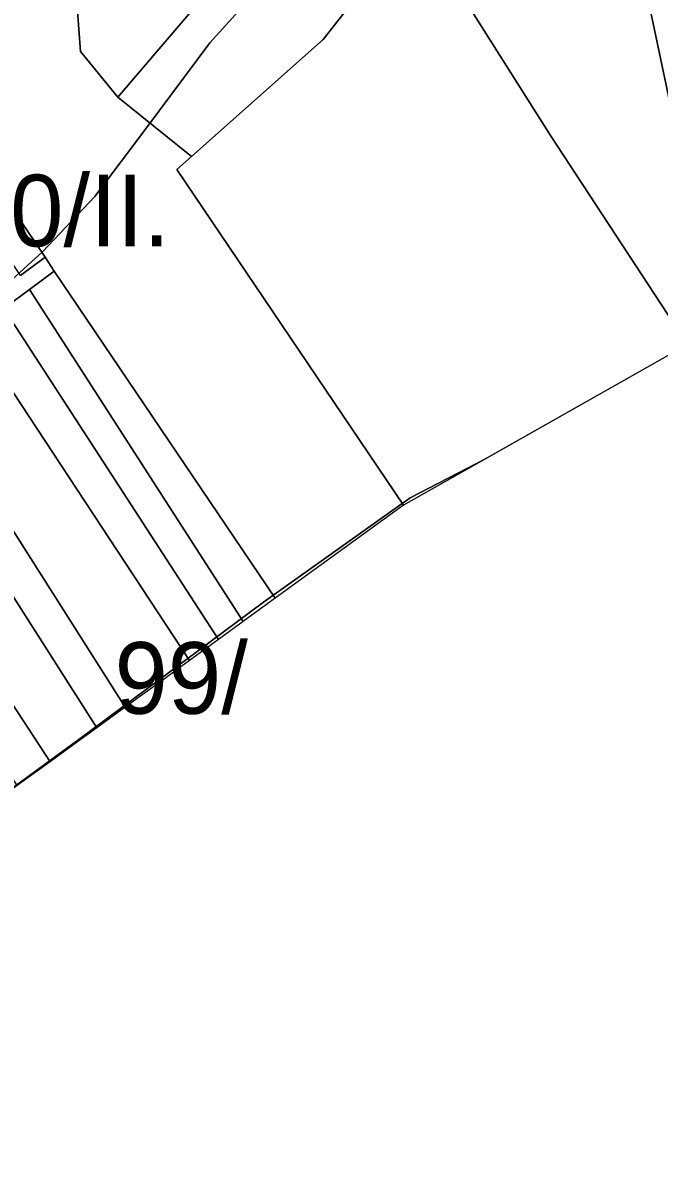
# Model space of a CAD drawing. Extents: x -535894 to -532827, y -1165802 to -1163635.
# Drawn here: x -534025 to -533891.9, y -1165422.7 to -1165184 of the extents above; entities that cross this region are included whole.
import ezdxf

# ---------------------------------------------------------------- set-up
doc = ezdxf.new("R2010")
doc.units = 0
for name, color, linetype in [('BPEJ_s', 7, 'Continuous'), ('orna_s', 7, 'Continuous'), ('ostatni_s', 7, 'Continuous'), ('trav_porost_s', 7, 'Continuous')]:
    doc.layers.add(name, color=color, linetype=linetype)

msp = doc.modelspace()

# ---------------------------------------------------------------- linework, layer by layer
at = {"layer": 'BPEJ_s'}
for points in [[(-533970.41, -1165171.07), (-533985.872, -1165188.218), (-533999.16, -1165206.031), (-534009.91, -1165220.44), (-534020.91, -1165231.99), (-534035.084, -1165244.865), (-534056.9, -1165261.54), (-534075.955, -1165274.993), (-534079.332, -1165277.377), (-534105.4, -1165298.17), (-534125.07, -1165313.86), (-534136.06, -1165324.773), (-534150.4, -1165346.2), (-534161.87, -1165369.29), (-534178.11, -1165393.66), (-534186.226, -1165403.375), (-534198.82, -1165412.93), (-534213.249, -1165419.389), (-534226.966, -1165422.497), (-534241.03, -1165422.65), (-534254.891, -1165420.26), (-534261.74, -1165417.867), (-534281.75, -1165380.99)], [(-534136.06, -1165324.773), (-534125.07, -1165313.86), (-534105.4, -1165298.17), (-534079.332, -1165277.377), (-534075.955, -1165274.993), (-534056.9, -1165261.54), (-534035.084, -1165244.865), (-534020.91, -1165231.99), (-534009.91, -1165220.44), (-533999.16, -1165206.031), (-533985.872, -1165188.218), (-533970.41, -1165171.07)], [(-533885.93, -1165251.42), (-533928.089, -1165275.274), (-533943.99, -1165283.5), (-533974.66, -1165305.36), (-534013.02, -1165333.89), (-534079.092, -1165382.22)]]:
    msp.add_lwpolyline(points, dxfattribs=at)
msp.add_lwpolyline([(-534075.22, -1165379.41), (-534079.092, -1165382.22), (-534013.02, -1165333.89), (-533974.66, -1165305.36), (-533943.99, -1165283.5), (-533928.089, -1165275.274), (-533945.33, -1165285.03), (-533972.2, -1165304.55), (-533978.9, -1165309.42), (-533984.1, -1165313.19), (-533990.15, -1165317.59), (-533996.63, -1165322.3), (-534003.61, -1165327.37), (-534009.54, -1165331.68), (-534014.32, -1165335.17), (-534019.31, -1165338.8), (-534026.18, -1165343.78), (-534031.82, -1165347.88), (-534037.71, -1165352.16), (-534044.14, -1165356.83), (-534052.73, -1165363.08), (-534059.04, -1165367.66), (-534067.65, -1165373.91)], close=True, dxfattribs=at)
at = {"layer": 'orna_s'}
msp.add_lwpolyline([(-534053.42, -1165184.18), (-534020.37, -1165233.16), (-534025.49, -1165236.98), (-534057.5, -1165188.56)], close=True, dxfattribs=at)
at = {"layer": 'ostatni_s'}
msp.add_lwpolyline([(-534025.49, -1165236.98), (-534020.37, -1165233.16), (-534018.44, -1165236.03), (-534023.58, -1165239.87), (-534028.98, -1165243.88)], dxfattribs=at)
at = {"layer": 'trav_porost_s'}
for points in [[(-533885.93, -1165251.42), (-533914.6, -1165207.64), (-533942.82, -1165162.9), (-533928.42, -1165147.92), (-533922.67, -1165144.99), (-533917.7, -1165142.45), (-533927.15, -1165125.06), (-533934.45, -1165116.87), (-533962.53, -1165085.32), (-533960.64, -1165083.51), (-533944.91, -1165074.95), (-533943.82, -1165067.47), (-533942.64, -1165066.34), (-533932.89, -1165078.2), (-533921.87, -1165077.16), (-533901.06, -1165073.37), (-533870.09, -1165067.22)], [(-533864.82, -1165157.28), (-533899.27, -1165133.08), (-533903.4, -1165135.17), (-533879.59, -1165248.35)]]:
    msp.add_lwpolyline(points, dxfattribs=at)
for points in [[(-533962.53, -1165085.32), (-533934.45, -1165116.87), (-533940.8, -1165124.3), (-534005.15, -1165199.61), (-534012.92, -1165190.05), (-534014.17, -1165173.12), (-534019.14, -1165162.52), (-534024.54, -1165159.35), (-534021.42, -1165157.14), (-534022.96, -1165151.54), (-534010.91, -1165138.64), (-533976.02, -1165098.2)], [(-533940.8, -1165124.3), (-533927.13, -1165137.47), (-533922.67, -1165144.99), (-533928.42, -1165147.92), (-533942.82, -1165162.9), (-533962.19, -1165187.57), (-533989.71, -1165212.03), (-534005.15, -1165199.61)], [(-533903.4, -1165135.17), (-533899.27, -1165133.08), (-533864.82, -1165157.28), (-533806.07, -1165212.59), (-533879.59, -1165248.35)], [(-534024.54, -1165159.35), (-534019.14, -1165162.52), (-534014.17, -1165173.12), (-534012.92, -1165190.05), (-534005.15, -1165199.61), (-533989.71, -1165212.03), (-533992.77, -1165214.76), (-533945.33, -1165285.03), (-533972.2, -1165304.55), (-534018.44, -1165236.03), (-534020.37, -1165233.16), (-534053.42, -1165184.18), (-534033.26, -1165162.58), (-534030.52, -1165163.57)], [(-533962.19, -1165187.57), (-533942.82, -1165162.9), (-533914.6, -1165207.64), (-533885.93, -1165251.42), (-533945.33, -1165285.03), (-533992.77, -1165214.76), (-533989.71, -1165212.03)], [(-534018.44, -1165236.03), (-533972.2, -1165304.55), (-533978.9, -1165309.42), (-534023.58, -1165239.87)], [(-534023.58, -1165239.87), (-533978.9, -1165309.42), (-533984.1, -1165313.19), (-534028.98, -1165243.88)], [(-534028.98, -1165243.88), (-533984.1, -1165313.19), (-533990.15, -1165317.59), (-534035.47, -1165248.71)], [(-534035.47, -1165248.71), (-533990.15, -1165317.59), (-533996.63, -1165322.3), (-534003.61, -1165327.37), (-534047.73, -1165257.84), (-534041.8, -1165253.42)], [(-534047.73, -1165257.84), (-534003.61, -1165327.37), (-534009.54, -1165331.68), (-534053.75, -1165262.31)], [(-534053.75, -1165262.31), (-534009.54, -1165331.68), (-534014.32, -1165335.17), (-534019.31, -1165338.8), (-534064.21, -1165270.09), (-534058.84, -1165266.1)], [(-534064.21, -1165270.09), (-534019.31, -1165338.8), (-534026.18, -1165343.78), (-534070.53, -1165274.8)]]:
    msp.add_lwpolyline(points, close=True, dxfattribs=at)

# ---------------------------------------------------------------- texts
at = {"layer": 'BPEJ_s'}
for s, p in [('35800/II.', (-534072.282, -1165230.865)), ('99/', (-534005.805, -1165328.747))]:
    msp.add_text(s, height=15, dxfattribs=at).set_placement(p)

doc.saveas('drawing.dxf')
